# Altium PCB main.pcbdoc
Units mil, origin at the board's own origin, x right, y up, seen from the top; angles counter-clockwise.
Board outline 4500 x 2900 mil, 2 copper layers (Top Layer, Bottom Layer); 63 components, 52 nets, 244 pads, 468 vias.
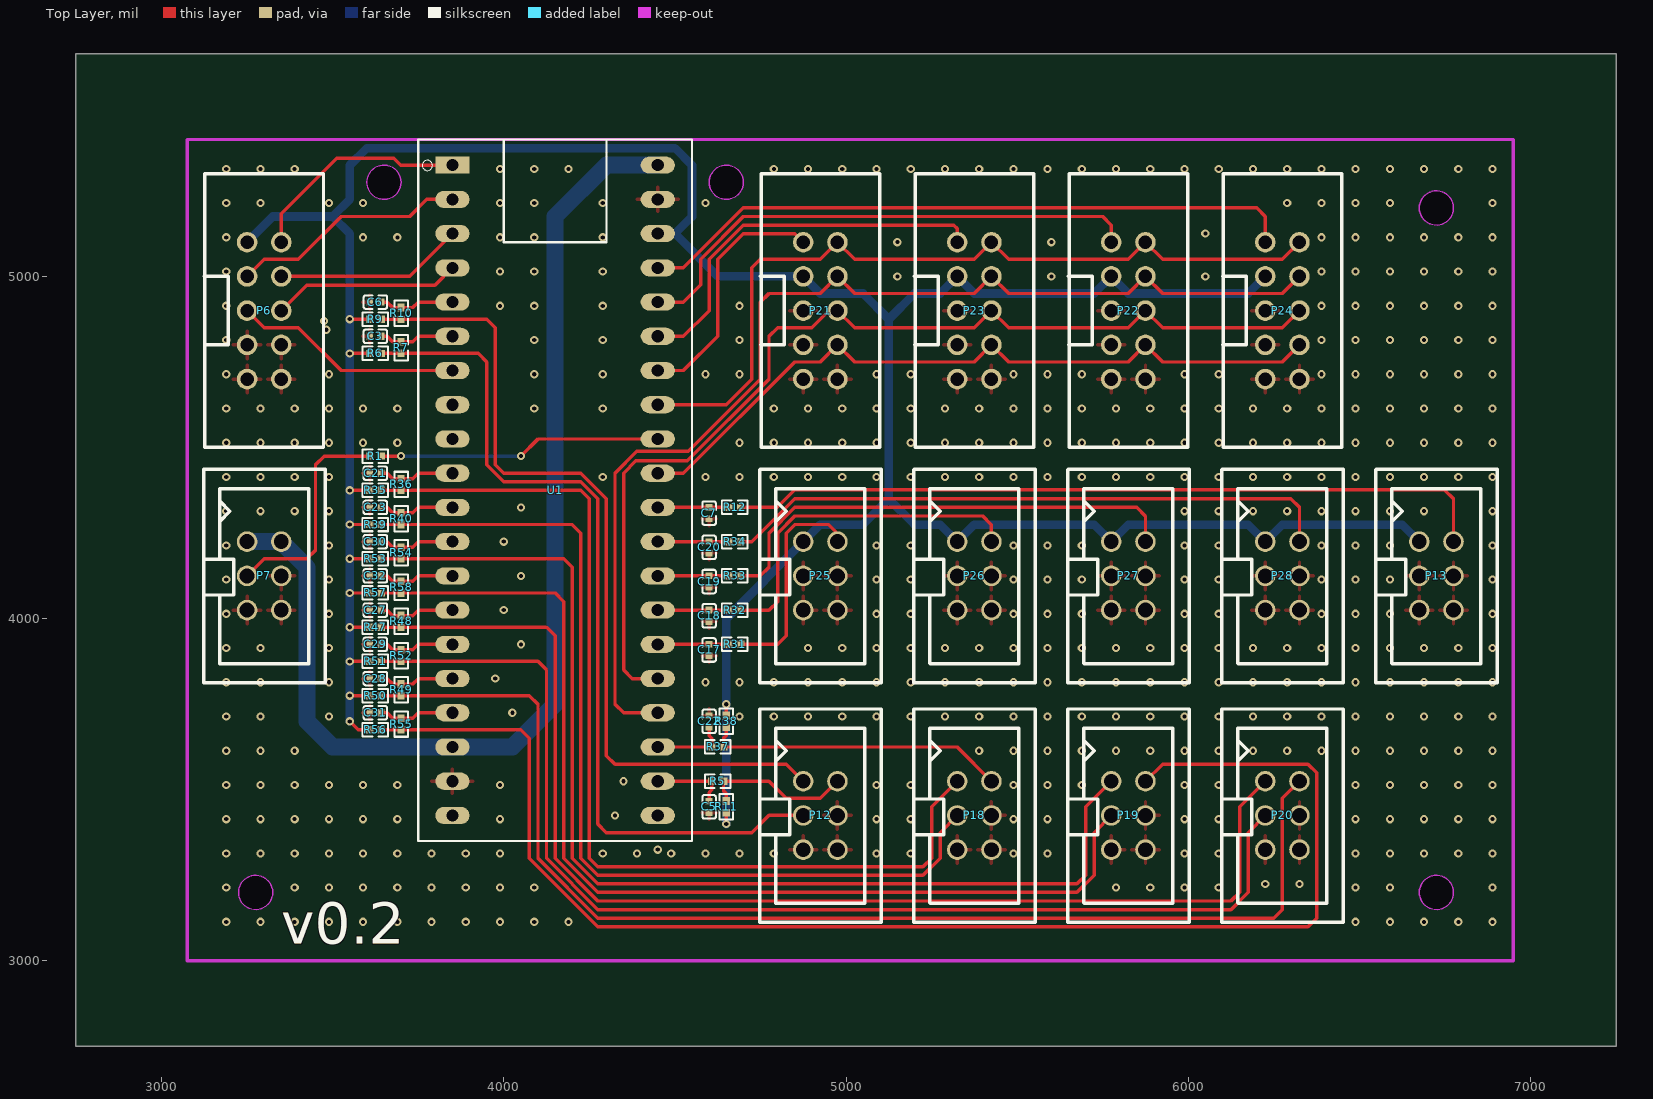
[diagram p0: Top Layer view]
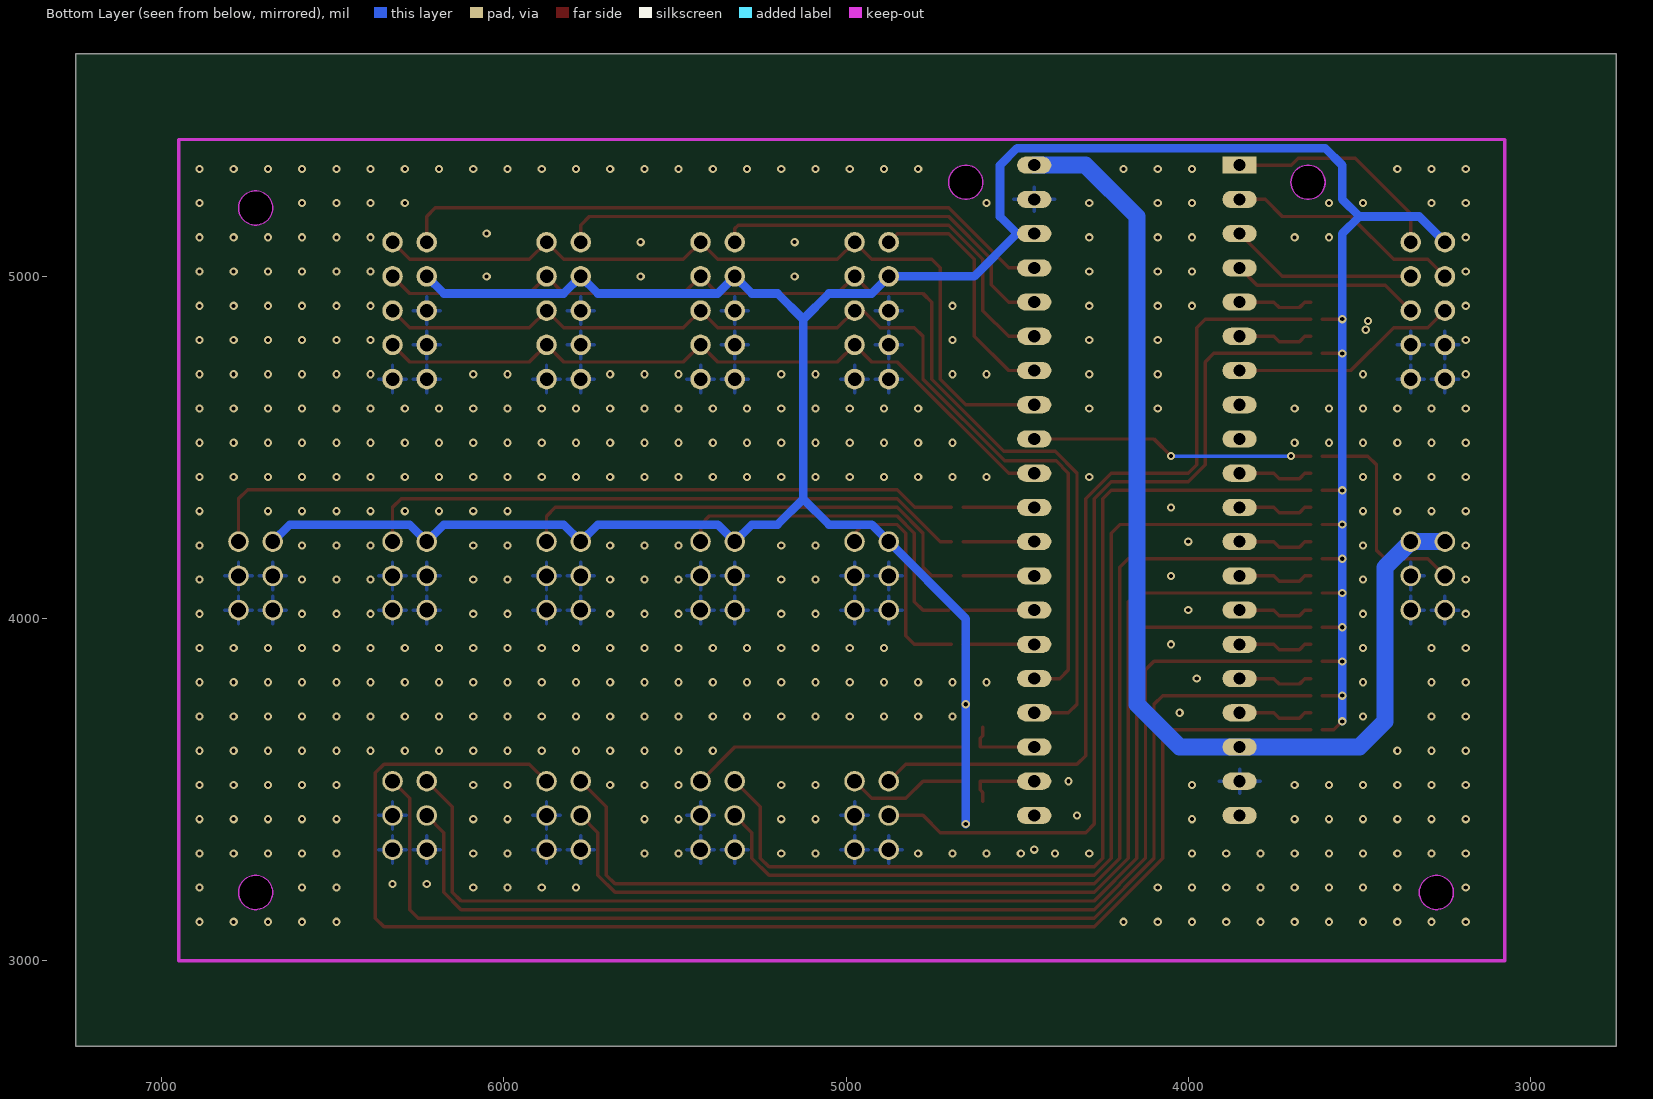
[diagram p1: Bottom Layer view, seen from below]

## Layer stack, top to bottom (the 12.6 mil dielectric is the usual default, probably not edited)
Top Layer: signal copper (thickness not stored)
Dielectric: dielectric 12.6, FR-4, Dk 4.8
Bottom Layer: signal copper (thickness not stored)

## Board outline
7250,2750 2750,2750 2750,5650 7250,5650
cut-out: 3700,5275 cw(c3650,5275) 3600,5275 cw(c3650,5275)
cut-out: 4700,5275 cw(c4650,5275) 4600,5275 cw(c4650,5275)
cut-out: 3325,3200 cw(c3275,3200) 3225,3200 cw(c3275,3200)
cut-out: 6775,3200 cw(c6725,3200) 6675,3200 cw(c6725,3200)
cut-out: 6775,5200 cw(c6725,5200) 6675,5200 cw(c6725,5200)

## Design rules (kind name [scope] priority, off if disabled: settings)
BoardOutlineClearance copperThickness1oz [All] p0: genericclearance=10 ignorepadtopadclearanceinfootprint=FALSE except(0: Arc-SplitContinuation Track-SplitContinuation SMDPad-SplitContinuation THPad-SplitContinuation Via-SplitContinuation Fill-SplitContinuation Poly-SplitContinuation Region-SplitContinuation Text-SplitContinuation; 6: Track-CutoutEdge SMDPad-CutoutEdge THPad-CutoutEdge Via-CutoutEdge Region-CutoutEdge; 11.8: Track-OutlineEdge SMDPad-OutlineEdge THPad-OutlineEdge Via-OutlineEdge Fill-OutlineEdge Region-OutlineEdge Poly-OutlineEdge Text-OutlineEdge Fill-CutoutEdge)
BoardOutlineClearance copperThickness2oz [All] p0: genericclearance=10 ignorepadtopadclearanceinfootprint=FALSE except(0: Arc-SplitContinuation Track-SplitContinuation SMDPad-SplitContinuation THPad-SplitContinuation Via-SplitContinuation Fill-SplitContinuation Poly-SplitContinuation Region-SplitContinuation Text-SplitContinuation; 6: Track-CutoutEdge SMDPad-CutoutEdge THPad-CutoutEdge Via-CutoutEdge Region-CutoutEdge; 11.8: Track-OutlineEdge SMDPad-OutlineEdge THPad-OutlineEdge Via-OutlineEdge Fill-OutlineEdge Region-OutlineEdge Poly-OutlineEdge Text-OutlineEdge Fill-CutoutEdge)
Clearance copperThickness1oz [(InNet('3V3') OR InNet('MX_SCK') OR InNet('MX_MISO') OR InNet('MX_MOSI') OR InNet('MX_ROWL') OR InNet('MX_COLL') OR InNet('GND') OR InNet('5V') OR InNet('$1N11636') OR InNet('$1N4893') OR InNet('$1N6245') OR InNet('LED') OR InNet('ENC0_A') OR InNet('ENC0_B') OR InNet('ENC1_A') OR InNet('ENC1_B') OR InNet('ENC2_A') OR InNet('ENC2_B') OR InNet('ENC3_A') OR InNet('ENC3_B') OR InNet('DP_RST') OR InNet('FAD0') OR InNet('FAD1') OR InNet('FAD2') OR InNet('FAD3') OR InNet('FAD4') OR InNet('DP_SCK') OR InNet('DP_MOSI') OR InNet('ENC0_BTN') OR InNet('ENC1_BTN') OR InNet('ENC2_BTN') OR InNet('ENC3_BTN') OR InNet('DP_DC') OR InNet('DP0_CS') OR InNet('DP1_CS') OR InNet('DP2_CS') OR InNet('DP3_CS') OR InNet('$1N10974') OR InNet('$1N15576') OR InNet('$1N18313') OR InNet('$1N18314') OR InNet('$1N18301') OR InNet('$1N20354') OR InNet('$1N20356') OR InNet('$1N20351') OR InNet('$1N19978') OR InNet('$1N19980') OR InNet('$1N19975') OR InNet('$1N32477') OR InNet('$1N32435') OR InNet('$1N32469') OR InNet('$1N32458'))] p1: gap=7 ignorepadtopadclearanceinfootprint=FALSE except(4: Track-Track; 6: Track-SMDPad SMDPad-SMDPad Track-THPad SMDPad-THPad THPad-THPad Track-Via SMDPad-Via THPad-Via Via-Via SMDPad-Fill THPad-Fill Via-Fill Fill-Fill Track-Region SMDPad-Region THPad-Region Via-Region Region-Region Track-Poly SMDPad-Poly THPad-Poly Via-Poly Fill-Poly Region-Poly Poly-Poly Track-Text SMDPad-Text THPad-Text Via-Text Fill-Text Region-Text Poly-Text Text-Text; 6.9: Track-Hole SMDPad-Hole THPad-Hole Via-Hole Fill-Hole Region-Hole Poly-Hole Text-Hole Sheet-Hole; 11.8: Track-Fill Fill-Region Track-Sheet SMDPad-Sheet THPad-Sheet Via-Sheet Fill-Sheet Region-Sheet Poly-Sheet Text-Sheet)
Clearance copperThickness2oz [All] p1: gap=7 ignorepadtopadclearanceinfootprint=FALSE except(6: Track-SMDPad SMDPad-SMDPad Track-THPad SMDPad-THPad THPad-THPad Track-Via SMDPad-Via THPad-Via Via-Via SMDPad-Fill THPad-Fill Via-Fill Fill-Fill Track-Region SMDPad-Region THPad-Region Via-Region Region-Region Track-Poly SMDPad-Poly THPad-Poly Via-Poly Fill-Poly Region-Poly Poly-Poly Track-Text SMDPad-Text THPad-Text Via-Text Fill-Text Region-Text Poly-Text Text-Text; 6.9: Track-Hole SMDPad-Hole THPad-Hole Via-Hole Fill-Hole Region-Hole Poly-Hole Text-Hole Sheet-Hole; 8: Track-Track; 11.8: Track-Fill Fill-Region Track-Sheet SMDPad-Sheet THPad-Sheet Via-Sheet Fill-Sheet Region-Sheet Poly-Sheet Text-Sheet)
DiffPairsRouting differentialPair [All] p1: maxuncoupledlength=10 minlimit=6 maxlimit=6 mostfreqgap=6 toplayer_minwidth=5 toplayer_prefwidth=10 toplayer_maxwidth=100 bottomlayer_minwidth=5 bottomlayer_prefwidth=10 bottomlayer_maxwidth=100
PasteMaskExpansion pasteMaskExpansion [All] p1: expansion=0
PlaneConnect innerPlane [All] p1: planeconnectstyle=Relief reliefexpansion=20 reliefentries=4 reliefconductorwidth=10 reliefairgap=10
PolygonConnect copperRegion [All] p1: connectstyle=Relief reliefentries=4 reliefconductorwidth=10 polygonreliefangle="90 Angle" airgapwidth=10
RoutingVias viaSize [All] p1: viastyle="Through Hole" holewidth=12.0078 minholewidth=11.811 maxholewidth=248.0314 width=24.0158 minwidth=19.685 maxwidth=393.7008
SolderMaskExpansion solderMaskExpansion [All] p1: useseparateexpansions=TRUE expansion=2 expansionbottom=2
Width copperThickness1oz [All] p1: maxlimit=100 minlimit=5 preferedwidth=10
Width copperThickness2oz [All] p1: maxlimit=100 minlimit=8 preferedwidth=10

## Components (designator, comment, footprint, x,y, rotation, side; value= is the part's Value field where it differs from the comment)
C3 "CL05B103KB5NNNC" C0402 3625,4825 r0 top
C5 "CL05B104KO5NNNC" C0402 4600,3450 r270 top
C6 "CL05B103KB5NNNC" C0402 3625,4925 r0 top
C7 "CL05B104KO5NNNC" C0402 4600,4308.46 r270 top
C17 "CL05B104KO5NNNC" C0402 4600,3908.46 r270 top
C18 "CL05B104KO5NNNC" C0402 4600,4008.46 r270 top
C19 "CL05B104KO5NNNC" C0402 4600,4108.46 r270 top
C20 "CL05B104KO5NNNC" C0402 4600,4208.46 r270 top
C21 "CL05B103KB5NNNC" C0402 3625,4425 r0 top
C22 "CL05B104KO5NNNC" C0402 4600,3700 r90 top
C23 "CL05B103KB5NNNC" C0402 3625,4325 r0 top
C27 "CL05B103KB5NNNC" C0402 3625,4025 r0 top
C28 "CL05B104KO5NNNC" C0402 3625,3825 r180 top
C29 "CL05B103KB5NNNC" C0402 3625,3925 r0 top
C30 "CL05B103KB5NNNC" C0402 3625,4225 r0 top
C31 "CL05B104KO5NNNC" C0402 3625,3725 r180 top
C32 "CL05B103KB5NNNC" C0402 3625,4125 r0 top
P6 "2.54-2*5P简牛" IDC-TH_10P-P2.54_C5665 3300,4900 r270 top
P7 "2.54-2*3P简牛" IDC-TH_6P-P2.54_C11214 3300,4125 r270 top
P12 "2.54-2*3P简牛" IDC-TH_6P-P2.54_C11214 4925,3425 r270 top
P13 "2.54-2*3P简牛" IDC-TH_6P-P2.54_C11214 6725,4125 r270 top locked
P18 "2.54-2*3P简牛" IDC-TH_6P-P2.54_C11214 5375,3425 r270 top
P19 "2.54-2*3P简牛" IDC-TH_6P-P2.54_C11214 5825,3425 r270 top
P20 "2.54-2*3P简牛" IDC-TH_6P-P2.54_C11214 6275,3425 r270 top
P21 "2.54-2*5P简牛" IDC-TH_10P-P2.54_C5665 4925,4900 r270 top
P22 "2.54-2*5P简牛" IDC-TH_10P-P2.54_C5665 5825,4900 r270 top
P23 "2.54-2*5P简牛" IDC-TH_10P-P2.54_C5665 5375,4900 r270 top
P24 "2.54-2*5P简牛" IDC-TH_10P-P2.54_C5665 6275,4900 r270 top
P25 "2.54-2*3P简牛" IDC-TH_6P-P2.54_C11214 4925,4125 r270 top locked
P26 "2.54-2*3P简牛" IDC-TH_6P-P2.54_C11214 5375,4125 r270 top locked
P27 "2.54-2*3P简牛" IDC-TH_6P-P2.54_C11214 5825,4125 r270 top locked
P28 "2.54-2*3P简牛" IDC-TH_6P-P2.54_C11214 6275,4125 r270 top locked
R1 "0402WGF4700TCE" R0402 3625,4475 r180 top
R5 "0402WGF1001TCE" R0402 4625,3525 r0 top
R6 "0402WGF1002TCE" R0402 3625,4775 r180 top
R7 "0402WGF1002TCE" R0402 3700,4792.04 r270 top
R9 "0402WGF1002TCE" R0402 3625,4875 r180 top
R10 "0402WGF1002TCE" R0402 3700,4892.04 r270 top
R11 "0402WGF1002TCE" R0402 4650,3450 r270 top
R12 "0402WGF1001TCE" R0402 4675,4325 r0 top
R31 "0402WGF1001TCE" R0402 4675,3925 r0 top
R32 "0402WGF1001TCE" R0402 4675,4025 r0 top
R33 "0402WGF1001TCE" R0402 4675,4125 r0 top
R34 "0402WGF1001TCE" R0402 4675,4225 r0 top
R35 "0402WGF1002TCE" R0402 3625,4375 r180 top
R36 "0402WGF1002TCE" R0402 3700,4392.04 r270 top
R37 "0402WGF1001TCE" R0402 4625,3625 r0 top
R38 "0402WGF1002TCE" R0402 4650,3700 r90 top
R39 "0402WGF1002TCE" R0402 3625,4275 r180 top
R40 "0402WGF1002TCE" R0402 3700,4292.04 r270 top
R47 "0402WGF1002TCE" R0402 3625,3975 r180 top
R48 "0402WGF1002TCE" R0402 3700,3992.04 r270 top
R49 "0402WGF1001TCE" R0402 3700,3792.04 r270 top
R50 "0402WGF1002TCE" R0402 3625,3775 r180 top
R51 "0402WGF1002TCE" R0402 3625,3875 r180 top
R52 "0402WGF1002TCE" R0402 3700,3892.04 r270 top
R53 "0402WGF1002TCE" R0402 3625,4175 r180 top
R54 "0402WGF1002TCE" R0402 3700,4192.04 r270 top
R55 "0402WGF1001TCE" R0402 3700,3692.04 r270 top
R56 "0402WGF1002TCE" R0402 3625,3675 r180 top
R57 "0402WGF1002TCE" R0402 3625,4075 r180 top
R58 "0402WGF1002TCE" R0402 3700,4092.04 r270 top
U1 "BlackPill" Z_module_black_pill_STM32F411 4150,4375 r270 top

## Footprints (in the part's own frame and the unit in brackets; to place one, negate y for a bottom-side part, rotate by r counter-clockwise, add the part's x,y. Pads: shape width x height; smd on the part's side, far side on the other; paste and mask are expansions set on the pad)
C0402 [mm]
  rect 0.5x0.54 smd: 1(-0.42,0) 2(0.42,0)
  silkscreen extent -0.87,-0.5 0.87,0.5
IDC-TH_6P-P2.54_C11214 [mil]
  round 60 hole 43.3: 1(-100,-50) 2(-100,50) 3(0,-50) 4(0,50) 5(100,-50) 6(100,50)
  silkscreen extent -311,-177 312,178
IDC-TH_10P-P2.54_C5665 [mil]
  round 60 hole 39.37: 1(-200,-50) 2(-200,50) 3(-100,-50) 4(-100,50) 5(0,-50) 6(0,50) 7(100,-50) 8(100,50) 9(200,-50) 10(200,50)
  silkscreen extent -400,-175 400,173
R0402 [mm]
  rect 0.566x0.54 smd: 1(-0.433,0) 2(0.433,0)
  silkscreen extent -0.94,-0.5 0.94,0.5
Z_module_black_pill_STM32F411 [mm]
  rect 1.27x2.54 hole 0.9: 1(-24.13,-7.62)
  oval 1.27x2.54 hole 0.9: 2(-21.59,-7.62) 3(-19.05,-7.62) 4(-16.51,-7.62) 5(-13.97,-7.62) 6(-11.43,-7.62) 7(-8.89,-7.62) 8(-6.35,-7.62) 9(-3.81,-7.62) 10(-1.27,-7.62) 11(1.27,-7.62) 12(3.81,-7.62) 13(6.35,-7.62) 14(8.89,-7.62) 15(11.43,-7.62) 16(13.97,-7.62) 17(16.51,-7.62) 18(19.05,-7.62) 19(21.59,-7.62) 20(24.13,-7.62) 21(24.13,7.62) 22(21.59,7.62) 23(19.05,7.62) 24(16.51,7.62) 25(13.97,7.62) 26(11.43,7.62) 27(8.89,7.62) 28(6.35,7.62) 29(3.81,7.62) 30(1.27,7.62) 31(-1.27,7.62) 32(-3.81,7.62) 33(-6.35,7.62) 34(-8.89,7.62) 35(-11.43,7.62) 36(-13.97,7.62) 37(-16.51,7.62) 38(-19.05,7.62) 39(-21.59,7.62) 40(-24.13,7.62)
  silkscreen extent -26.04,-10.16 26.04,10.16

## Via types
v1: diameter 24.02, hole 12.01, Top Layer to Bottom Layer, 468 vias

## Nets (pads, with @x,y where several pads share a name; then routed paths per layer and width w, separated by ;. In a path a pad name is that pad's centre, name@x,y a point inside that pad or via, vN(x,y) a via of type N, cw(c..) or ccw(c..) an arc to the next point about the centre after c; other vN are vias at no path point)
3V3: P6.1 P13.1 P21.3 P22.3 P23.3 P24.3 P25.1 P26.1 P27.1 P28.1 R6.2 R9.2 R11.2 R35.2 R38.2 R39.2 R47.2 R50.2 R51.2 R53.2 R56.2 R57.2 U1.38 | length 9349.7
  Top Layer w10: v1(3550,3700) 3575,3675 R56.2 ; v1(3550,3775) R50.2 ; v1(3550,3875) R51.2 ; v1(3550,3975) R47.2 ; v1(3550,4075) R57.2 ; v1(3550,4175) R53.2 ; v1(3550,4275) R39.2 ; v1(3550,4375) R35.2 ; v1(3550,4775) R6.2 ; v1(3550,4875) R9.2 ; v1(4650,3400) R11.2 ; R38.2 v1(4650,3750)
  Bottom Layer w25: P6.1 3325,5175 3500,5175 ; v1(3550,3700) v1(3550,3775) v1(3550,3875) v1(3550,3975) v1(3550,4075) v1(3550,4175) v1(3550,4275) v1(3550,4375) v1(3550,4775) v1(3550,4875) 3550,5125 3500,5175 ; U1.38 4500,5125 ; v1(4650,3400) v1(4650,3750) 4650,4000 P25.1 4925,4275 5050,4275 5125,4350 ; P24.3 6175,4950 5825,4950 P22.3 5725,4950 5375,4950 P23.3 5275,4950 5200,4950 5125,4875 ; P13.1 6625,4275 6275,4275 P28.1 6175,4275 5825,4275 P27.1 5725,4275 5375,4275 P26.1 5275,4275 5200,4275 5125,4350 ; 3500,5175 3550,5225 3550,5325 3600,5375 4500,5375 4550,5325 4550,5175 4500,5125 ; 4500,5125 4625,5000 P21.3 4925,4950 5050,4950 5125,4875 ; 5125,4350 5125,4875
5V: P7.1 P7.2 U1.18 U1.40 | length 3251
  Bottom Layer w50: P7.1 P7.2 3425,4150 3425,3700 3500,3625 U1.18 4025,3625 4150,3750 4150,5175 4300,5325 U1.40
$1N4893: P12.1 R9.1 R10.2 | length 2465.8
  Top Layer w10: R9.1 R10.2 3950,4875 3975,4850 3975,4450 4000,4425 4225,4425 4300,4350 4300,3600 4325,3575 4825,3575 P12.1
$1N6245: P12.3 R6.1 R7.2 | length 2565.8
  Top Layer w10: R6.1 R7.2 3925,4775 3950,4750 3950,4450 4000,4400 4225,4400 4275,4350 4275,3400 4300,3375 4725,3375 4775,3425 P12.3
$1N10974: P26.2 R32.2 | length 1016.4
  Top Layer w10: R32.2@4700,4025 4775,4025 4800,4050 4800,4250 4850,4300 5400,4300 5425,4275 P26.2
$1N11636: P7.3 R1.2 | length 649.4
  Top Layer w10: P7.3 3300,4175 3425,4175 3450,4200 3450,4450 3475,4475 R1.2
$1N15576: P12.2 R5.2 R11.1 | length 435.6
  Top Layer w10: R11.1 4650,3489.16 4642.04,3497.12 R5.2 4775,3525 4825,3475 4925,3475 P12.2
$1N18301: P18.3 R39.1 R40.2 | length 2780.4
  Top Layer w10: R39.1 R40.2 4200,4275 4225,4250 4225,3300 4275,3250 5225,3250 5275,3300 5275,3375 P18.3
$1N18313: P18.1 R35.1 R36.2 | length 2945.1
  Top Layer w10: R35.1 R36.2 4225,4375 4250,4350 4250,3300 4275,3275 5225,3275 5250,3300 5250,3450 P18.1
$1N18314: P18.2 R37.2 R38.1 | length 885.6
  Top Layer w10: R38.1 4650,3657.96 4642.04,3650 R37.2 5325,3625 P18.2
$1N19975: P20.3 R51.1 R52.2 | length 3421.9
  Top Layer w10: R51.1 R52.2 4100,3875 4125,3850 4125,3300 4275,3150 6125,3150 6175,3200 6175,3375 P20.3
$1N19978: P20.1 R47.1 R48.2 | length 3586.5
  Top Layer w10: R47.1 R48.2 4125,3975 4150,3950 4150,3300 4275,3175 6125,3175 6150,3200 6150,3450 P20.1
$1N19980: P20.2 R49.2 R50.1 | length 3571.9
  Top Layer w10: R50.1 R49.2 4075,3775 4100,3750 4100,3300 4275,3125 6250,3125 6275,3150 6275,3475 P20.2
$1N20351: P19.3 R57.1 R58.2 | length 3101.2
  Top Layer w10: R57.1 R58.2 4150,4075 4175,4050 4175,3300 4275,3200 5675,3200 5725,3250 5725,3375 P19.3
$1N20354: P19.1 R53.1 R54.2 | length 3265.8
  Top Layer w10: R53.1 R54.2 4175,4175 4200,4150 4200,3300 4275,3225 5675,3225 5700,3250 5700,3450 P19.1
$1N20356: P19.2 R55.2 R56.1 | length 4142.6
  Top Layer w10: R56.1 R55.2 4050,3675 4075,3650 4075,3300 4275,3100 6350,3100 6375,3125 6375,3550 6350,3575 5925,3575 P19.2
$1N32435: P25.2 R31.2 | length 639
  Top Layer w10: R31.2 4800,3925 4825,3950 4825,4250 4850,4275 4950,4275 4975,4250 P25.2
$1N32458: P28.2 R34.2 | length 1795.1
  Top Layer w10: R34.2 4725,4225 4850,4350 6300,4350 6325,4325 P28.2
$1N32469: P27.2 R33.2 | length 1409.7
  Top Layer w10: R33.2 4750,4125 4775,4150 4775,4250 4850,4325 5850,4325 5875,4300 P27.2
$1N32477: P13.2 R12.2 | length 2240.3
  Top Layer w10: R12.2 4798.51,4325 4850,4376.49 6748.51,4376.49 6775,4350 P13.2
DP0_CS: P21.1 U1.34 | length 732.8
  Top Layer w10: U1.34 4525,4725 4625,4825 4625,5050 4700,5125 4850,5125 P21.1
DP1_CS: P23.1 U1.35 | length 1141.6
  Top Layer w10: U1.35 4525,4825 4600,4900 4600,5050 4700,5150 5315,5150 5325,5140 P23.1
DP2_CS: P22.1 U1.36 | length 1532.8
  Top Layer w10: U1.36 4525,4925 4575,4975 4575,5050 4700,5175 5750,5175 5775,5150 P22.1
DP3_CS: P24.1 U1.37 | length 1932.8
  Top Layer w10: U1.37 4525,5025 4700,5200 6200,5200 6225,5175 P24.1
DP_DC: P21.4 P22.4 P23.4 P24.4 U1.24 | length 3304.6
  Top Layer w10: U1.24 4350,3725 4325,3750 4325,4425 4389.02,4489.02 4539.02,4489.02 4750,4700 4750,4925 4775,4950 4925,4950 P21.4 5025,4950 5375,4950 P23.4 5475,4950 5825,4950 P22.4 5925,4950 6275,4950 P24.4
DP_MOSI: P21.2 P22.2 P23.2 P24.2 U1.33 | length 2386.4
  Top Layer w10: U1.33 4650,4625 4725,4700 4725,5025 4750,5050 4925,5050 P21.2 5025,5050 5375,5050 P23.2 5475,5050 5825,5050 P22.2 5925,5050 6275,5050 P24.2
DP_RST: P21.6 P22.6 P23.6 P24.6 U1.25 | length 3054.6
  Top Layer w10: U1.25 4375,3825 4350,3850 4350,4425 4385.98,4460.98 4535.98,4460.98 4775,4700 4775,4825 4800,4850 4900,4850 4950,4900 P21.6 5025,4850 5375,4850 P23.6 5475,4850 5825,4850 P22.6 5925,4850 6275,4850 P24.6
DP_SCK: P21.8 P22.8 P23.8 P24.8 U1.31 | length 2154.6
  Top Layer w10: U1.31 4525,4425 4850,4750 4925,4750 P21.8 5025,4750 5375,4750 P23.8 5475,4750 5825,4750 P22.8 5925,4750 6275,4750 P24.8
ENC0_A: C6.2 R10.1 U1.5 | length 221.6
  Top Layer w10: C6.2 3659.08,4925 3675,4909.08 R10.1 3734.08,4909.08 3750,4925 U1.5
ENC0_B: C3.2 R7.1 U1.6 | length 221.6
  Top Layer w10: C3.2 3659.08,4825 3675,4809.08 R7.1 3734.08,4809.08 3750,4825 U1.6
ENC0_BTN: C5.1 R5.1 U1.22 | length 219.7
  Top Layer w10: U1.22 R5.1 4607.96,3500 4600,3492.04 C5.1
ENC1_A: C21.2 R36.1 U1.10 | length 221.6
  Top Layer w10: C21.2 3659.08,4425 3675,4409.08 R36.1 3734.08,4409.08 3750,4425 U1.10
ENC1_B: C23.2 R40.1 U1.11 | length 221.6
  Top Layer w10: C23.2 3659.08,4325 3675,4309.08 R40.1 3734.08,4309.08 3750,4325 U1.11
ENC1_BTN: C22.1 R37.1 U1.23 | length 219.7
  Top Layer w10: U1.23 R37.1 4607.96,3650 4600,3657.96 C22.1
ENC2_A: C30.2 R54.1 U1.12 | length 221.6
  Top Layer w10: C30.2 3659.08,4225 3675,4209.08 R54.1 3734.08,4209.08 3750,4225 U1.12
ENC2_B: C32.2 R58.1 U1.13 | length 221.6
  Top Layer w10: C32.2 3659.08,4125 3675,4109.08 R58.1 3734.08,4109.08 3750,4125 U1.13
ENC2_BTN: C31.1 R55.1 U1.17 | length 221.6
  Top Layer w10: C31.1 3659.08,3725 3675,3709.08 R55.1 3734.08,3709.08 3750,3725 U1.17
ENC3_A: C27.2 R48.1 U1.14 | length 221.6
  Top Layer w10: C27.2 3659.08,4025 3675,4009.08 R48.1 3734.08,4009.08 3750,4025 U1.14
ENC3_B: C29.2 R52.1 U1.15 | length 221.6
  Top Layer w10: C29.2 3659.08,3925 3675,3909.08 R52.1 3734.08,3909.08 3750,3925 U1.15
ENC3_BTN: C28.1 R49.1 U1.16 | length 221.6
  Top Layer w10: C28.1 3659.08,3825 3675,3809.08 R49.1 3734.08,3809.08 3750,3825 U1.16
FAD0: C17.1 R31.1 U1.26 | length 208
  Top Layer w10: U1.26 C17.1 R31.1
FAD1: C18.1 R32.1 U1.27 | length 208
  Top Layer w10: U1.27 C18.1 R32.1
FAD2: C19.1 R33.1 U1.28 | length 208
  Top Layer w10: U1.28 C19.1 R33.1
FAD3: C20.1 R34.1 U1.29 | length 208
  Top Layer w10: U1.29 C20.1 R34.1
FAD4: C7.1 R12.1 U1.30 | length 208
  Top Layer w10: U1.30 C7.1 R12.1
GND: C3.1 C5.2 C6.1 C7.2 C17.2 C18.2 C19.2 C20.2 C21.1 C22.2 C23.1 C27.1 C28.2 C29.1 C30.1 C31.2 C32.1 P6.7 P6.8 P6.9 P6.10 P7.4 P7.5 P7.6 P12.4 P12.5 P12.6 P13.3 P13.4 P13.5 P13.6 P18.4 P18.5 P18.6 P19.4 P19.5 P19.6 P20.4 P20.5 P20.6 P21.5 P21.7 P21.9 P21.10 P22.5 P22.7 P22.9 P22.10 P23.5 P23.7 P23.9 P23.10 P24.5 P24.7 P24.9 P24.10 P25.3 P25.4 P25.5 P25.6 P26.3 P26.4 P26.5 P26.6 P27.3 P27.4 P27.5 P27.6 P28.3 P28.4 P28.5 P28.6 U1.19 U1.39
  other v1: 3189.1,3114.1 3289.1,3114.1 3389.1,3114.1 3489.1,3114.1 3589.1,3114.1 3689.1,3114.1 3789.1,3114.1 3889.1,3114.1 3989.1,3114.1 4089.1,3114.1 4189.1,3114.1 6489.1,3114.1 6589.1,3114.1 6689.1,3114.1 6789.1,3114.1 6889.1,3114.1 3189.1,3214.1 3389.1,3214.1 3489.1,3214.1 3589.1,3214.1 3689.1,3214.1 3789.1,3214.1 3889.1,3214.1 3989.1,3214.1 4089.1,3214.1 5789.1,3214.1 5889.1,3214.1 5989.1,3214.1 6089.1,3214.1 6489.1,3214.1 6589.1,3214.1 6889.1,3214.1 6225,3225 6325,3225 3189.1,3314.1 3289.1,3314.1 3389.1,3314.1 3489.1,3314.1 3589.1,3314.1 3689.1,3314.1 3789.1,3314.1 3889.1,3314.1 3989.1,3314.1 4289.1,3314.1 4389.1,3314.1 4489.1,3314.1 4589.1,3314.1 4689.1,3314.1 4789.1,3314.1 5089.1,3314.1 5189.1,3314.1 5489.1,3314.1 5589.1,3314.1 5989.1,3314.1 6089.1,3314.1 6489.1,3314.1 6589.1,3314.1 6689.1,3314.1 6789.1,3314.1 6889.1,3314.1 4450,3325 3189.1,3414.1 3289.1,3414.1 3389.1,3414.1 3489.1,3414.1 3589.1,3414.1 3689.1,3414.1 3989.1,3414.1 5089.1,3414.1 5189.1,3414.1 5489.1,3414.1 5589.1,3414.1 5989.1,3414.1 6089.1,3414.1 6489.1,3414.1 6589.1,3414.1 6689.1,3414.1 6789.1,3414.1 6889.1,3414.1 4325,3425 3189.1,3514.1 3289.1,3514.1 3389.1,3514.1 3489.1,3514.1 3589.1,3514.1 3689.1,3514.1 3989.1,3514.1 5089.1,3514.1 5189.1,3514.1 5489.1,3514.1 5589.1,3514.1 5689.1,3514.1 5989.1,3514.1 6089.1,3514.1 6489.1,3514.1 6589.1,3514.1 6689.1,3514.1 6789.1,3514.1 6889.1,3514.1 4350,3525 3189.1,3614.1 3289.1,3614.1 3389.1,3614.1 5389.1,3614.1 5489.1,3614.1 5589.1,3614.1 5689.1,3614.1 5789.1,3614.1 5889.1,3614.1 5989.1,3614.1 6089.1,3614.1 6189.1,3614.1 6289.1,3614.1 6389.1,3614.1 6489.1,3614.1 6589.1,3614.1 6689.1,3614.1 6789.1,3614.1 6889.1,3614.1 3189.1,3714.1 3289.1,3714.1 3489.1,3714.1 4689.1,3714.1 4789.1,3714.1 4889.1,3714.1 4989.1,3714.1 5089.1,3714.1 5189.1,3714.1 5289.1,3714.1 5389.1,3714.1 5489.1,3714.1 5589.1,3714.1 5689.1,3714.1 5789.1,3714.1 5889.1,3714.1 5989.1,3714.1 6089.1,3714.1 6189.1,3714.1 6289.1,3714.1 6389.1,3714.1 6489.1,3714.1 6589.1,3714.1 6689.1,3714.1 6789.1,3714.1 6889.1,3714.1 4025,3725 3189.1,3814.1 3289.1,3814.1 3489.1,3814.1 4589.1,3814.1 4689.1,3814.1 4789.1,3814.1 4889.1,3814.1 4989.1,3814.1 5089.1,3814.1 5189.1,3814.1 5289.1,3814.1 5389.1,3814.1 5489.1,3814.1 5589.1,3814.1 5689.1,3814.1 5789.1,3814.1 5889.1,3814.1 5989.1,3814.1 6089.1,3814.1 6189.1,3814.1 6289.1,3814.1 6389.1,3814.1 6489.1,3814.1 6589.1,3814.1 6689.1,3814.1 6789.1,3814.1 6889.1,3814.1 3975,3825 3189.1,3914.1 3289.1,3914.1 3489.1,3914.1 4889.1,3914.1 4989.1,3914.1 5089.1,3914.1 5189.1,3914.1 5289.1,3914.1 5389.1,3914.1 5489.1,3914.1 5589.1,3914.1 5689.1,3914.1 5789.1,3914.1 5889.1,3914.1 5989.1,3914.1 6089.1,3914.1 6189.1,3914.1 6289.1,3914.1 6389.1,3914.1 6489.1,3914.1 6589.1,3914.1 6689.1,3914.1 6789.1,3914.1 6889.1,3914.1 4050,3925 3189.1,4014.1 3489.1,4014.1 5089.1,4014.1 5189.1,4014.1 5489.1,4014.1 5589.1,4014.1 5689.1,4014.1 5989.1,4014.1 6089.1,4014.1 6389.1,4014.1 6489.1,4014.1 6589.1,4014.1 6889.1,4014.1 4000,4025 3189.1,4114.1 3489.1,4114.1 5089.1,4114.1 5189.1,4114.1 5489.1,4114.1 5589.1,4114.1 5689.1,4114.1 5989.1,4114.1 6089.1,4114.1 6389.1,4114.1 6489.1,4114.1 6589.1,4114.1 6889.1,4114.1 4050,4125 3189.1,4214.1 3489.1,4214.1 5089.1,4214.1 5189.1,4214.1 5489.1,4214.1 5589.1,4214.1 5689.1,4214.1 5989.1,4214.1 6089.1,4214.1 6389.1,4214.1 6489.1,4214.1 6589.1,4214.1 6889.1,4214.1 4000,4225 3189.1,4314.1 3289.1,4314.1 3389.1,4314.1 3489.1,4314.1 5989.1,4314.1 6089.1,4314.1 6189.1,4314.1 6289.1,4314.1 6389.1,4314.1 6489.1,4314.1 6589.1,4314.1 6689.1,4314.1 6889.1,4314.1 4050,4325 3189.1,4414.1 3289.1,4414.1 3389.1,4414.1 3489.1,4414.1 4289.1,4414.1 4589.1,4414.1 4689.1,4414.1 4789.1,4414.1 4889.1,4414.1 4989.1,4414.1 5089.1,4414.1 5189.1,4414.1 5289.1,4414.1 5389.1,4414.1 5489.1,4414.1 5589.1,4414.1 5689.1,4414.1 5789.1,4414.1 5889.1,4414.1 5989.1,4414.1 6089.1,4414.1 6189.1,4414.1 6289.1,4414.1 6389.1,4414.1 6489.1,4414.1 6589.1,4414.1 6689.1,4414.1 6789.1,4414.1 6889.1,4414.1 3189.1,4514.1 3289.1,4514.1 3389.1,4514.1 3489.1,4514.1 3589.1,4514.1 3689.1,4514.1 4689.1,4514.1 4789.1,4514.1 4889.1,4514.1 4989.1,4514.1 5089.1,4514.1 5189.1,4514.1 5289.1,4514.1 5389.1,4514.1 5489.1,4514.1 5589.1,4514.1 5689.1,4514.1 5789.1,4514.1 5889.1,4514.1 5989.1,4514.1 6089.1,4514.1 6189.1,4514.1 6289.1,4514.1 6389.1,4514.1 6489.1,4514.1 6589.1,4514.1 6689.1,4514.1 6789.1,4514.1 6889.1,4514.1 3189.1,4614.1 3289.1,4614.1 3389.1,4614.1 3489.1,4614.1 3589.1,4614.1 3689.1,4614.1 4089.1,4614.1 4289.1,4614.1 4789.1,4614.1 4889.1,4614.1 4989.1,4614.1 5089.1,4614.1 5189.1,4614.1 5289.1,4614.1 5389.1,4614.1 5489.1,4614.1 5589.1,4614.1 5689.1,4614.1 5789.1,4614.1 5889.1,4614.1 5989.1,4614.1 6089.1,4614.1 6189.1,4614.1 6289.1,4614.1 6389.1,4614.1 6489.1,4614.1 6589.1,4614.1 6689.1,4614.1 6789.1,4614.1 6889.1,4614.1 3189.1,4714.1 3489.1,4714.1 4089.1,4714.1 4289.1,4714.1 4589.1,4714.1 4689.1,4714.1 5089.1,4714.1 5189.1,4714.1 5489.1,4714.1 5589.1,4714.1 5689.1,4714.1 5989.1,4714.1 6089.1,4714.1 6389.1,4714.1 6489.1,4714.1 6589.1,4714.1 6689.1,4714.1 6789.1,4714.1 6889.1,4714.1 3189.1,4814.1 4089.1,4814.1 4289.1,4814.1 4689.1,4814.1 6389.1,4814.1 6489.1,4814.1 6589.1,4814.1 6689.1,4814.1 6789.1,4814.1 6889.1,4814.1 3481.46,4844.1 3475,4869.45 3189.1,4914.1 3989.1,4914.1 4089.1,4914.1 4289.1,4914.1 4689.1,4914.1 6389.1,4914.1 6489.1,4914.1 6589.1,4914.1 6689.1,4914.1 6789.1,4914.1 6889.1,4914.1 5150,5000 5600,5000 6050,5000 3189.1,5014.1 3989.1,5014.1 4089.1,5014.1 4289.1,5014.1 6389.1,5014.1 6489.1,5014.1 6589.1,5014.1 6689.1,5014.1 6789.1,5014.1 6889.1,5014.1 5150,5100 5600,5100 3189.1,5114.1 3589.1,5114.1 3689.1,5114.1 3989.1,5114.1 4089.1,5114.1 4289.1,5114.1 6389.1,5114.1 6489.1,5114.1 6589.1,5114.1 6689.1,5114.1 6789.1,5114.1 6889.1,5114.1 6050,5125 3189.1,5214.1 3289.1,5214.1 3489.1,5214.1 3589.1,5214.1 3989.1,5214.1 4089.1,5214.1 4289.1,5214.1 4589.1,5214.1 6289.1,5214.1 6389.1,5214.1 6489.1,5214.1 6589.1,5214.1 6889.1,5214.1 3189.1,5314.1 3289.1,5314.1 3389.1,5314.1 3989.1,5314.1 4089.1,5314.1 4189.1,5314.1 4789.1,5314.1 4889.1,5314.1 4989.1,5314.1 5089.1,5314.1 5189.1,5314.1 5289.1,5314.1 5389.1,5314.1 5489.1,5314.1 5589.1,5314.1 5689.1,5314.1 5789.1,5314.1 5889.1,5314.1 5989.1,5314.1 6089.1,5314.1 6189.1,5314.1 6289.1,5314.1 6389.1,5314.1 6489.1,5314.1 6589.1,5314.1 6689.1,5314.1 6789.1,5314.1 6889.1,5314.1
LED: R1.1 U1.32 | length 828.7
  Top Layer w10: R1.1 v1(3700,4475) ; v1(4050,4475) 4100,4525 U1.32
  Bottom Layer w10: v1(3700,4475) v1(4050,4475)
MX_COLL: P6.5 U1.7 | length 672.5
  Top Layer w10: P6.5 3300,4850 3400,4850 3525,4725 U1.7
MX_MISO: P6.4 U1.3 | length 551.8
  Top Layer w10: P6.4 3725,5000 U1.3
MX_MOSI: P6.6 U1.4 | length 551.8
  Top Layer w10: P6.6 3424.08,4974.08 3799.08,4974.08 U1.4
MX_ROWL: P6.2 U1.1 | length 658.1
  Top Layer w10: P6.2 3350,5182.52 3512.52,5345.04 3679.01,5345.04 3699.05,5325 U1.1
MX_SCK: P6.3 U1.2 | length 693.2
  Top Layer w10: P6.3 3300,5050 3400,5050 3525,5175 3725,5175 3775,5225 U1.2
pads on no net: U1.8 U1.9 U1.20 U1.21

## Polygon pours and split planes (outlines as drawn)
GND on Top Layer (solid, remove dead copper, pour order 0): 3000,5400 7000,5400 7000,3000 3000,3000
GND on Bottom Layer (solid, remove dead copper, pour order 2): 3000,5400 7000,5400 7000,3000 3000,3000

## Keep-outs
Board Outline Layer:
  circle w1: c3650,5275 r50
  region: 3700,5275 cw(c3650,5275) 3600,5275 cw(c3650,5275)
  circle w1: c4650,5275 r50
  region: 4700,5275 cw(c4650,5275) 4600,5275 cw(c4650,5275)
  circle w1: c3275,3200 r50
  region: 3325,3200 cw(c3275,3200) 3225,3200 cw(c3275,3200)
  circle w1: c6725,3200 r50
  region: 6775,3200 cw(c6725,3200) 6675,3200 cw(c6725,3200)
  circle w1: c6725,5200 r50
  region: 6775,5200 cw(c6725,5200) 6675,5200 cw(c6725,5200)
  lines w10: 3075,3000 6950,3000 6950,5400 3075,5400 3075,3000

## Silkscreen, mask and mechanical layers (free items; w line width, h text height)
Top Silkscreen Layer:
  text "v0.2" at 3350,3050 h120
Mechanical Layer:
  circle w1: c3650,5275 r50
  circle w1: c4650,5275 r50
  circle w1: c3275,3200 r50
  circle w1: c6725,3200 r50
  circle w1: c6725,5200 r50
